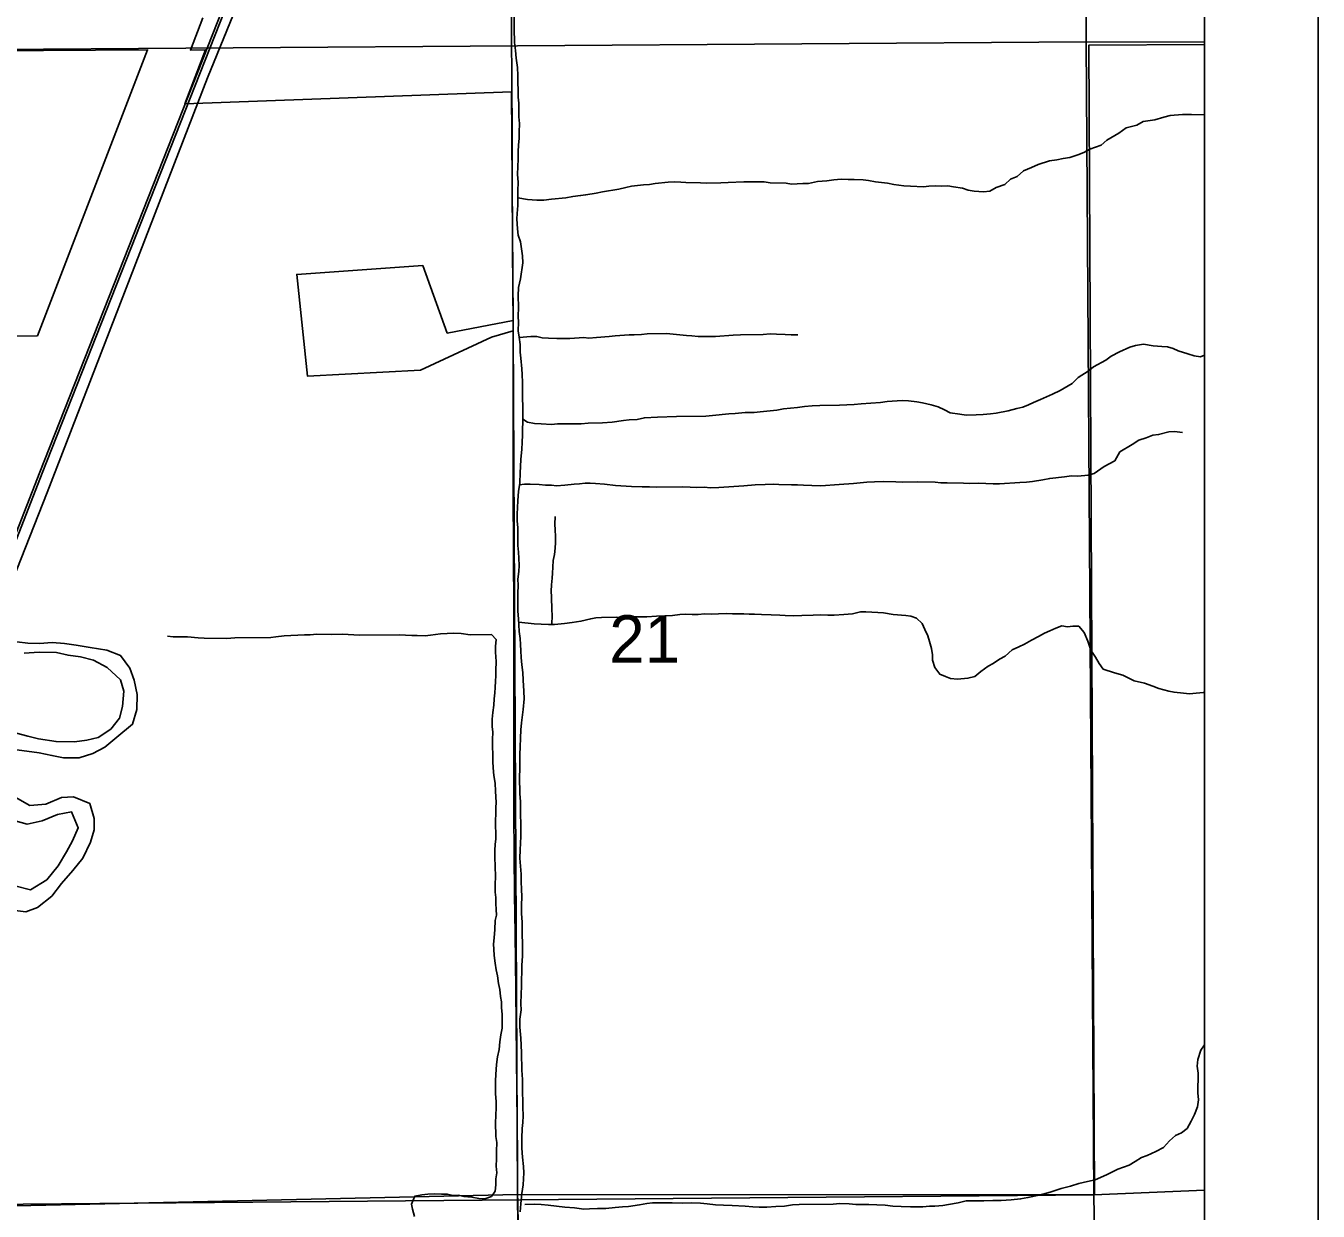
# Model space of a CAD drawing. Extents: x 0 to 34, y 0 to 22.
# Drawn here: x 7.864 to 9, y 17.862 to 18.904 of the extents above; entities that cross this region are included whole.
import ezdxf

# ---------------------------------------------------------------- set-up
doc = ezdxf.new("R2010")
doc.units = 0
for name, color, linetype in [('Default', 7, 'Continuous'), ('GM_X_County_Road', 7, 'Continuous'), ('GM_X_Minor_River', 7, 'Continuous'), ('GM_X_Rail_Line', 7, 'Continuous'), ('GM_X_Section', 7, 'Continuous'), ('GM_X_Section_Text', 7, 'Continuous'), ('GM_X_State_Route', 7, 'Continuous'), ('SH_Data', 7, 'Continuous')]:
    doc.layers.add(name, color=color, linetype=linetype)

msp = doc.modelspace()

# ---------------------------------------------------------------- linework, layer by layer
at = {"layer": 'Default'}
for points in [[(8.9, 18.8897), (8.9, 19.8895), (8.7909, 19.8887), (8.796, 18.8901)], [(8.9, 17.8804), (8.9, 18.8897), (8.796, 18.8901), (8.8027, 17.8763)], [(8.9, 16.8757), (8.9, 17.8804), (8.8027, 17.8763), (8.8106, 17.3801), (8.802, 16.8756)]]:
    msp.add_lwpolyline(points, close=True, dxfattribs=at)
for points in [[(7.7898, 17.3636), (8.3, 17.3879), (8.2997, 17.4193), (8.2996, 17.4628), (8.2992, 17.5498), (8.2973, 17.7551), (8.2966, 17.8142), (8.2964, 17.8483), (8.296, 17.8766), (8.2922, 18.636), (8.2732, 18.6304), (8.2109, 18.6013), (8.1114, 18.5961), (8.102, 18.6855), (8.2128, 18.6932), (8.2343, 18.6339), (8.2922, 18.6449), (8.2909, 18.8461), (8.0037, 18.8355), (8.0219, 18.883), (8.0085, 18.8827), (8.0194, 18.9112)], [(7.7881, 18.8817), (7.9709, 18.883), (7.874, 18.6316), (7.8353, 18.6309)]]:
    msp.add_lwpolyline(points, dxfattribs=at)
at = {"layer": 'GM_X_County_Road'}
msp.add_line((8.2924, 18.6354), (8.2924, 18.6444), dxfattribs=at)
for points in [[(8.2911, 18.8456), (8.2907, 18.906), (8.2905, 18.9401), (8.29, 19.0082), (8.2898, 19.0423), (8.2899, 19.0857), (8.2898, 19.1136), (8.2897, 19.1353), (8.29, 19.1539), (8.2902, 19.2096), (8.2895, 19.2654), (8.2896, 19.315), (8.2896, 19.3521), (8.2895, 19.3846)], [(8.2924, 18.6444), (8.2921, 18.6709), (8.2917, 18.7116), (8.2915, 18.7678), (8.2913, 18.8178), (8.2911, 18.8456)], [(8.2962, 17.8761), (8.2961, 17.91), (8.2952, 17.997), (8.2946, 18.0561), (8.294, 18.1059), (8.2936, 18.1401), (8.293, 18.2116), (8.2929, 18.2613), (8.2928, 18.3048), (8.2928, 18.3888), (8.2924, 18.4945), (8.2922, 18.5411), (8.2924, 18.5876), (8.2923, 18.6061), (8.2924, 18.6354)], [(8.3002, 17.3874), (8.2999, 17.4187), (8.2998, 17.4622), (8.2994, 17.5493), (8.2975, 17.7545), (8.2968, 17.8136), (8.2966, 17.8478), (8.2963, 17.8707), (8.2962, 17.8761)]]:
    msp.add_lwpolyline(points, dxfattribs=at)
at = {"layer": 'GM_X_Minor_River'}
for points in [[(8.2929, 18.9356), (8.2933, 18.9014), (8.2935, 18.8893), (8.2943, 18.8824), (8.2948, 18.8756), (8.296, 18.8673), (8.2965, 18.8604), (8.2967, 18.8414), (8.2972, 18.8361), (8.2974, 18.824), (8.2978, 18.8183), (8.2975, 18.8107), (8.2976, 18.805), (8.2969, 18.7993), (8.2966, 18.7932), (8.2967, 18.7867), (8.2964, 18.7803), (8.2961, 18.7734), (8.2966, 18.7666), (8.2963, 18.759), (8.2965, 18.7461), (8.2958, 18.7392), (8.2955, 18.7343), (8.296, 18.7256), (8.2968, 18.7199), (8.2988, 18.7142), (8.2996, 18.7081), (8.3005, 18.7017), (8.3009, 18.6956), (8.2988, 18.6815), (8.297, 18.6739), (8.2967, 18.6667), (8.2969, 18.6568), (8.2966, 18.6485), (8.297, 18.6435), (8.2968, 18.6359), (8.2976, 18.6302), (8.2984, 18.6238), (8.2985, 18.617), (8.299, 18.612), (8.2998, 18.6025), (8.3003, 18.5976)], [(8.2964, 18.7529), (8.3048, 18.7515), (8.3131, 18.7509), (8.3192, 18.7509), (8.3261, 18.7518), (8.3386, 18.7527), (8.3447, 18.7539), (8.3515, 18.7548), (8.3561, 18.7556), (8.3652, 18.7569), (8.3709, 18.7581), (8.3853, 18.7606), (8.3913, 18.7618), (8.3963, 18.763), (8.4069, 18.7643), (8.4122, 18.7647), (8.4172, 18.7655), (8.4286, 18.7665), (8.4339, 18.7669), (8.4396, 18.7666), (8.4442, 18.7663), (8.4571, 18.7661), (8.4624, 18.7658), (8.475, 18.7659), (8.4814, 18.7664), (8.4951, 18.767), (8.5004, 18.767), (8.513, 18.7668), (8.5183, 18.7661), (8.5324, 18.7656), (8.537, 18.7649), (8.5469, 18.7654), (8.5518, 18.7654), (8.5598, 18.7671), (8.5681, 18.7679), (8.5742, 18.7688), (8.5807, 18.7692), (8.5867, 18.7689), (8.5921, 18.769), (8.6001, 18.7687), (8.6046, 18.768), (8.6107, 18.767), (8.6214, 18.7656), (8.6271, 18.7645), (8.6359, 18.7635), (8.6416, 18.7632), (8.653, 18.7626), (8.6576, 18.763), (8.6633, 18.7635), (8.669, 18.7632), (8.6743, 18.7633), (8.6793, 18.7626), (8.6873, 18.7612), (8.6922, 18.7597), (8.6976, 18.7586), (8.7059, 18.758), (8.7113, 18.7588), (8.7169, 18.7619), (8.7245, 18.7647), (8.7294, 18.7693), (8.7354, 18.7717), (8.7411, 18.7767), (8.7479, 18.7794), (8.7539, 18.7822), (8.7638, 18.7853), (8.7702, 18.7862), (8.7759, 18.7874), (8.7816, 18.7882), (8.7888, 18.7906), (8.7941, 18.7926), (8.7994, 18.7957), (8.8092, 18.7992), (8.8141, 18.8035), (8.8247, 18.8097), (8.8311, 18.8144), (8.8406, 18.8168), (8.8462, 18.8199), (8.8565, 18.8215), (8.8644, 18.8239), (8.8698, 18.8251), (8.8808, 18.826), (8.8888, 18.8261), (8.8998, 18.8259), (8.9, 18.8259)], [(8.2976, 18.63), (8.3079, 18.6308), (8.3132, 18.6308), (8.3178, 18.6298), (8.3235, 18.6295), (8.3307, 18.6292), (8.3421, 18.6293), (8.3543, 18.6299), (8.3588, 18.6295), (8.3657, 18.63), (8.3767, 18.6309), (8.382, 18.6314), (8.3942, 18.6323), (8.3987, 18.6323), (8.4052, 18.6328), (8.4101, 18.6333), (8.4272, 18.6335), (8.4448, 18.6318), (8.4493, 18.6315), (8.455, 18.6308), (8.4703, 18.631), (8.4858, 18.632), (8.4923, 18.6325), (8.5121, 18.6327), (8.5181, 18.6332), (8.5239, 18.6329), (8.5315, 18.6326), (8.5368, 18.6323), (8.5425, 18.6324)], [(8.3008, 18.5581), (8.305, 18.5555), (8.3111, 18.5545), (8.3168, 18.5542), (8.326, 18.5535), (8.3313, 18.554), (8.3522, 18.5542), (8.3583, 18.5547), (8.3708, 18.5549), (8.3792, 18.5557), (8.3894, 18.557), (8.3944, 18.5575), (8.4012, 18.5579), (8.4077, 18.5595), (8.4191, 18.5601), (8.4358, 18.5607), (8.4617, 18.561), (8.4674, 18.5615), (8.4818, 18.5628), (8.4875, 18.5633), (8.4962, 18.5641), (8.5042, 18.5642), (8.5095, 18.5647), (8.524, 18.566), (8.53, 18.5672), (8.5422, 18.5685), (8.5483, 18.5694), (8.5551, 18.5699), (8.5619, 18.5703), (8.5791, 18.5706), (8.592, 18.5711), (8.5981, 18.5716), (8.6068, 18.5724), (8.6152, 18.5729), (8.6212, 18.5738), (8.6342, 18.5747), (8.6399, 18.5744), (8.6471, 18.5734), (8.6521, 18.5727), (8.6597, 18.5709), (8.6658, 18.569), (8.6715, 18.5665), (8.6765, 18.5639), (8.6849, 18.5625), (8.6906, 18.5618), (8.6994, 18.5619), (8.7054, 18.5624), (8.7119, 18.5628), (8.7168, 18.5636), (8.7275, 18.5657), (8.735, 18.5677), (8.7403, 18.5689), (8.7453, 18.5709), (8.7498, 18.5728), (8.7559, 18.5756), (8.7664, 18.5803), (8.7732, 18.5834), (8.7838, 18.5896), (8.7891, 18.595), (8.7977, 18.6004), (8.8026, 18.6043), (8.8132, 18.6101), (8.8181, 18.6136), (8.8253, 18.6175), (8.8344, 18.6214), (8.8393, 18.623), (8.8465, 18.6242), (8.8549, 18.6228), (8.8625, 18.6222), (8.8675, 18.6219), (8.8724, 18.6204), (8.877, 18.6182), (8.8854, 18.6156), (8.8911, 18.6138), (8.8965, 18.6131), (8.9, 18.6146)], [(8.3003, 18.5976), (8.3004, 18.5904), (8.3008, 18.5555), (8.3005, 18.5494), (8.3006, 18.5441), (8.3003, 18.538), (8.3, 18.5315), (8.299, 18.5231), (8.2987, 18.5163), (8.2984, 18.5114), (8.2981, 18.5019), (8.2971, 18.4946), (8.2964, 18.4866), (8.2961, 18.4802), (8.2958, 18.4749), (8.2959, 18.4688), (8.2963, 18.4627), (8.2965, 18.4471), (8.297, 18.4414), (8.2974, 18.4361), (8.2975, 18.4297), (8.2972, 18.4244), (8.2965, 18.4175), (8.2966, 18.4122), (8.2963, 18.405), (8.2964, 18.397), (8.2965, 18.3894), (8.297, 18.3826), (8.2974, 18.3773), (8.2975, 18.3716), (8.2984, 18.3655), (8.2988, 18.3602), (8.2989, 18.3545), (8.2993, 18.3488), (8.2998, 18.3423), (8.3007, 18.3355), (8.3011, 18.3287), (8.3016, 18.3192), (8.3021, 18.3124), (8.3011, 18.3029), (8.2997, 18.2911), (8.299, 18.285), (8.2987, 18.2778), (8.2985, 18.2702), (8.2982, 18.2633), (8.2983, 18.2508), (8.298, 18.2436), (8.2982, 18.2291), (8.2987, 18.2219), (8.2991, 18.1912), (8.2985, 18.1797), (8.2982, 18.1721), (8.2987, 18.1653), (8.2992, 18.1581), (8.2992, 18.1509), (8.2997, 18.1456), (8.2998, 18.1376), (8.2995, 18.1315), (8.2996, 18.1235), (8.3001, 18.116), (8.3005, 18.0863), (8.2998, 18.078), (8.2999, 18.0726), (8.2996, 18.065), (8.2997, 18.0593), (8.2994, 18.0529), (8.2991, 18.0441), (8.2992, 18.0388), (8.2981, 18.0308), (8.2982, 18.0236), (8.2991, 18.0141), (8.2992, 18.0077), (8.2997, 18.0012), (8.2999, 17.9857), (8.3004, 17.9777), (8.3004, 17.9716), (8.3007, 17.9534), (8.3012, 17.9458), (8.3009, 17.9397), (8.3002, 17.9344), (8.2999, 17.926), (8.3, 17.9173), (8.3005, 17.9093), (8.3014, 17.901), (8.3018, 17.8957), (8.3012, 17.885), (8.2998, 17.8774), (8.2991, 17.8683), (8.2984, 17.8614)], [(8.2979, 18.5004), (8.3023, 18.5012), (8.3073, 18.5012), (8.3152, 18.5009), (8.3206, 18.5003), (8.3259, 18.5003), (8.3305, 18.4996), (8.3377, 18.5001), (8.346, 18.501), (8.3506, 18.5014), (8.3555, 18.5019), (8.3601, 18.5019), (8.3647, 18.5016), (8.3727, 18.501), (8.3822, 18.4999), (8.3963, 18.499), (8.4058, 18.4987), (8.4123, 18.4988), (8.418, 18.4985), (8.4412, 18.4988), (8.448, 18.4985), (8.4537, 18.4982), (8.4602, 18.4983), (8.4659, 18.498), (8.4731, 18.4981), (8.4819, 18.4986), (8.4952, 18.4995), (8.505, 18.5004), (8.5138, 18.5009), (8.521, 18.501), (8.526, 18.5007), (8.537, 18.5005), (8.5423, 18.5006), (8.5476, 18.5002), (8.5549, 18.5), (8.5629, 18.4997), (8.5788, 18.5007), (8.5914, 18.5016), (8.6031, 18.5029), (8.61, 18.503), (8.6176, 18.5034), (8.6286, 18.5032), (8.6347, 18.5029), (8.648, 18.5031), (8.6632, 18.5029), (8.6682, 18.5022), (8.6739, 18.5023), (8.6883, 18.5021), (8.6937, 18.5018), (8.7013, 18.5019), (8.7142, 18.5013), (8.7199, 18.5014), (8.7378, 18.5024), (8.7435, 18.5028), (8.7488, 18.5033), (8.7579, 18.5049), (8.764, 18.5062), (8.7769, 18.5075), (8.7833, 18.5083), (8.7887, 18.508), (8.7978, 18.5089), (8.8031, 18.5105), (8.8118, 18.5167), (8.8212, 18.5217), (8.8257, 18.5294), (8.8366, 18.536), (8.8423, 18.5399), (8.8487, 18.5418), (8.8548, 18.5442), (8.8597, 18.5447), (8.8688, 18.5471), (8.8737, 18.5475), (8.8806, 18.5465)], [(8.3264, 18.3776), (8.3266, 18.386), (8.3262, 18.3906), (8.326, 18.4019), (8.3256, 18.4069), (8.3259, 18.4126), (8.3266, 18.4183), (8.3269, 18.4229), (8.3272, 18.4282), (8.3275, 18.4339), (8.3286, 18.4392), (8.3293, 18.4449), (8.3296, 18.4499), (8.3295, 18.4552), (8.3291, 18.4609), (8.329, 18.4658), (8.3293, 18.4726)], [(8.2972, 18.3798), (8.3107, 18.3782), (8.3168, 18.3779), (8.3233, 18.3776), (8.3286, 18.3777), (8.3374, 18.3785), (8.3442, 18.3794), (8.3518, 18.3806), (8.3605, 18.3827), (8.3651, 18.3835), (8.37, 18.3839), (8.3833, 18.3841), (8.3913, 18.3838), (8.3989, 18.3843), (8.4099, 18.3845), (8.4183, 18.3849), (8.4255, 18.3854), (8.4324, 18.3855), (8.4388, 18.3864), (8.4441, 18.3868), (8.4498, 18.3865), (8.4548, 18.3866), (8.4605, 18.387), (8.4666, 18.3867), (8.4727, 18.3872), (8.4795, 18.3873), (8.4852, 18.387), (8.4902, 18.387), (8.4951, 18.3871), (8.4997, 18.3868), (8.5046, 18.3869), (8.5107, 18.3866), (8.5191, 18.3863), (8.5267, 18.386), (8.5313, 18.3857), (8.5389, 18.3854), (8.5461, 18.3855), (8.556, 18.386), (8.5621, 18.3861), (8.5689, 18.3858), (8.5746, 18.3859), (8.583, 18.3864), (8.5906, 18.3872), (8.5978, 18.3888), (8.6023, 18.3889), (8.613, 18.3883), (8.6179, 18.388), (8.6263, 18.3866), (8.6374, 18.3856), (8.6419, 18.3849), (8.6469, 18.3834), (8.6519, 18.3786), (8.6543, 18.3733), (8.657, 18.3676), (8.6582, 18.3627), (8.6602, 18.3566), (8.661, 18.3509), (8.6611, 18.3464), (8.6631, 18.34), (8.6673, 18.3339), (8.6723, 18.3321), (8.6769, 18.3303), (8.683, 18.3296), (8.6921, 18.3305), (8.6982, 18.3321), (8.7034, 18.3363), (8.7098, 18.341), (8.7144, 18.3433), (8.72, 18.3472), (8.7249, 18.3499), (8.7309, 18.3553), (8.737, 18.358), (8.7419, 18.3604), (8.7479, 18.3639), (8.754, 18.367), (8.7593, 18.3701), (8.7642, 18.3721), (8.7695, 18.3744), (8.7748, 18.3764), (8.7797, 18.3757), (8.7843, 18.3761), (8.7896, 18.3762), (8.7943, 18.3706), (8.7974, 18.363), (8.8002, 18.3551), (8.8044, 18.3491), (8.8075, 18.3434), (8.811, 18.3385), (8.821, 18.3352), (8.8282, 18.333), (8.8382, 18.3282), (8.8473, 18.3261), (8.8546, 18.3235), (8.8599, 18.3213), (8.8687, 18.3191), (8.8733, 18.3181), (8.8817, 18.3174), (8.887, 18.3167), (8.8927, 18.3172), (8.8992, 18.318), (8.9, 18.3181)], [(7.8561, 18.2676), (7.8755, 18.2648), (7.8868, 18.2626), (7.8971, 18.2604), (7.9107, 18.2605), (7.9228, 18.2644), (7.9334, 18.2697), (7.9439, 18.2785), (7.9575, 18.29), (7.9616, 18.303), (7.9618, 18.3162), (7.9591, 18.3287), (7.9552, 18.3393), (7.9472, 18.3503), (7.9351, 18.3551), (7.9203, 18.3576), (7.9081, 18.3594), (7.8979, 18.3609), (7.8869, 18.3619), (7.8759, 18.3611), (7.8657, 18.3614), (7.8559, 18.3625)], [(7.9884, 18.3674), (7.9933, 18.3668), (8.0059, 18.3669), (8.0154, 18.3659), (8.0207, 18.3656), (8.0405, 18.3655), (8.0477, 18.366), (8.0793, 18.3664), (8.0838, 18.3668), (8.0911, 18.3677), (8.1089, 18.3687), (8.1139, 18.3687), (8.1196, 18.3692), (8.1325, 18.369), (8.1424, 18.3691), (8.1572, 18.3682), (8.1922, 18.3686), (8.2032, 18.368), (8.2078, 18.3681), (8.215, 18.3678), (8.2196, 18.3682), (8.2283, 18.3695), (8.2401, 18.37), (8.2466, 18.3697), (8.2546, 18.3687), (8.2732, 18.369), (8.2775, 18.3645), (8.2768, 18.3584), (8.2768, 18.3534), (8.2773, 18.3451), (8.2771, 18.3371), (8.2771, 18.3325), (8.2768, 18.328), (8.2765, 18.3223), (8.2762, 18.3177), (8.2755, 18.3124), (8.2752, 18.3067), (8.2745, 18.3002), (8.2738, 18.2945), (8.2739, 18.2881), (8.2743, 18.2831), (8.274, 18.2767), (8.2743, 18.2573), (8.2747, 18.2516), (8.2752, 18.2448), (8.2764, 18.2383), (8.2769, 18.2311), (8.277, 18.2262), (8.2774, 18.2212), (8.2771, 18.2167), (8.2772, 18.211), (8.2769, 18.2057), (8.2771, 18.1893), (8.2764, 18.1844), (8.2761, 18.1794), (8.2761, 18.1741), (8.2766, 18.1639), (8.2767, 18.157), (8.2765, 18.1483), (8.2765, 18.1422), (8.277, 18.1377), (8.277, 18.1324), (8.2775, 18.127), (8.2776, 18.1221), (8.2765, 18.1175), (8.2762, 18.1096), (8.2755, 18.1023), (8.2749, 18.0966), (8.2753, 18.0921), (8.2757, 18.0868), (8.2766, 18.0799), (8.2774, 18.0742), (8.2786, 18.0689), (8.2795, 18.0621), (8.2807, 18.0568), (8.2812, 18.0507), (8.282, 18.0458), (8.282, 18.0409), (8.2825, 18.0348), (8.2827, 18.0227), (8.2816, 18.0169), (8.2805, 18.0108), (8.2799, 18.004), (8.2784, 17.9975), (8.2777, 17.9907), (8.2771, 17.9819), (8.2768, 17.9766), (8.2769, 17.9652), (8.2774, 17.958), (8.2775, 17.9535), (8.2772, 17.9455), (8.2769, 17.9401), (8.277, 17.9276), (8.2779, 17.9223), (8.2776, 17.9147), (8.2777, 17.9079), (8.2774, 17.9014), (8.2778, 17.8957), (8.2772, 17.8904), (8.2772, 17.8851), (8.2765, 17.8794)], [(7.8624, 18.3526), (7.8756, 18.3535), (7.8908, 18.3532), (7.901, 18.3507), (7.912, 18.3492), (7.9234, 18.3463), (7.9355, 18.3399), (7.947, 18.329), (7.9501, 18.3192), (7.949, 18.3055), (7.9461, 18.2953), (7.9386, 18.2857), (7.9276, 18.2784), (7.9174, 18.2761), (7.9068, 18.2745), (7.8905, 18.2747), (7.875, 18.2773), (7.8655, 18.2795), (7.8557, 18.2821)], [(7.8545, 18.1262), (7.8639, 18.1251), (7.8741, 18.129), (7.8866, 18.1389), (7.8952, 18.15), (7.9053, 18.1615), (7.914, 18.1721), (7.9207, 18.1862), (7.924, 18.1972), (7.924, 18.2071), (7.9201, 18.2203), (7.9057, 18.2263), (7.8951, 18.2255), (7.8815, 18.2197), (7.8675, 18.2184), (7.8545, 18.2259)], [(7.8513, 18.2058), (7.8649, 18.2021), (7.8782, 18.2052), (7.8917, 18.2107), (7.9039, 18.213), (7.91, 18.199), (7.9048, 18.1876), (7.8995, 18.1777), (7.8924, 18.1655), (7.8823, 18.1533), (7.868, 18.1445), (7.8543, 18.1478)], [(8.3025, 17.8676), (8.3109, 17.868), (8.317, 17.8677), (8.3231, 17.8671), (8.3376, 17.8654), (8.3463, 17.8647), (8.3543, 17.8637), (8.3593, 17.8638), (8.3665, 17.8642), (8.3737, 17.8643), (8.3821, 17.8652), (8.3885, 17.8657), (8.3938, 17.8661), (8.4033, 17.8674), (8.4098, 17.8686), (8.4147, 17.8691), (8.4322, 17.8693), (8.441, 17.869), (8.4493, 17.8691), (8.4569, 17.8688), (8.463, 17.8682), (8.4703, 17.8675), (8.4771, 17.8672), (8.4847, 17.8669), (8.4962, 17.8663), (8.503, 17.8657), (8.5087, 17.8654), (8.5152, 17.8654), (8.5232, 17.8659), (8.5308, 17.8664), (8.538, 17.8673), (8.5437, 17.8677), (8.5737, 17.8681), (8.5794, 17.8686), (8.5878, 17.8683), (8.5935, 17.8676), (8.6049, 17.8678), (8.6121, 17.8675), (8.6194, 17.8672), (8.6262, 17.8662), (8.6335, 17.8659), (8.6415, 17.8656), (8.6525, 17.8658), (8.6582, 17.8662), (8.6631, 17.8663), (8.67, 17.8667), (8.6749, 17.8676), (8.6836, 17.8692), (8.6905, 17.8708), (8.706, 17.871), (8.714, 17.8711), (8.7213, 17.8712), (8.73, 17.8717), (8.7384, 17.8726), (8.7448, 17.8738), (8.7547, 17.8758), (8.7645, 17.8786), (8.774, 17.8818), (8.7823, 17.8838), (8.7895, 17.8862), (8.7971, 17.8878), (8.8039, 17.8894), (8.8138, 17.8937), (8.824, 17.8988), (8.8338, 17.9023), (8.8391, 17.9055), (8.8448, 17.909), (8.8497, 17.9109), (8.8572, 17.9144), (8.864, 17.9179), (8.8693, 17.9237), (8.8746, 17.9283), (8.8799, 17.9307), (8.8847, 17.9346), (8.8885, 17.9411), (8.8914, 17.9468), (8.894, 17.9537), (8.8947, 17.9598), (8.8942, 17.9658), (8.8942, 17.9715), (8.8945, 17.9776), (8.8944, 17.9833), (8.8935, 17.9894), (8.8942, 17.9951), (8.8968, 18.0035), (8.9, 18.0081)], [(8.2765, 17.8794), (8.2732, 17.8748), (8.2675, 17.8728), (8.2622, 17.8731), (8.2561, 17.8742), (8.2488, 17.8748), (8.2442, 17.8759), (8.2397, 17.8755), (8.2343, 17.8769), (8.2294, 17.8768), (8.2229, 17.8771), (8.2172, 17.8767), (8.2119, 17.8762), (8.2058, 17.875), (8.2029, 17.8681), (8.2037, 17.8636), (8.2057, 17.8572)]]:
    msp.add_lwpolyline(points, dxfattribs=at)
at = {"layer": 'GM_X_Rail_Line'}
for points in [[(7.4155, 16.9797), (7.4558, 17.1778), (7.5178, 17.4999), (7.5426, 17.6225), (7.5717, 17.7043), (7.6321, 17.8584), (7.8825, 18.4937), (8.0236, 18.8584), (8.1515, 19.1722), (8.1675, 19.2314), (8.3282, 19.8945)], [(7.1956, 16.9797), (7.2748, 17.1151), (7.3911, 17.3137), (7.4282, 17.3794), (7.4457, 17.4145), (7.4643, 17.4578), (7.6315, 17.8854), (7.7259, 18.128), (7.7853, 18.2725), (7.8783, 18.5108), (8.1687, 19.2471)], [(7.7606, 18.2123), (7.7831, 18.2734), (7.8762, 18.5116), (8.1665, 19.2479)]]:
    msp.add_lwpolyline(points, dxfattribs=at)
at = {"layer": 'GM_X_Section'}
for points in [[(7.782, 19.8851), (8.7909, 19.8887), (8.796, 18.8901), (7.7959, 18.8831)], [(8.796, 18.8901), (8.8027, 17.8763), (7.7942, 17.8673), (7.7959, 18.8831)], [(7.9972, 16.8792), (8.802, 16.8756), (8.8106, 17.3801), (8.8027, 17.8763), (7.7942, 17.8673), (7.7942, 17.5709), (7.8062, 16.9797), (7.9972, 16.9797)]]:
    msp.add_lwpolyline(points, close=True, dxfattribs=at)
at = {"layer": 'GM_X_State_Route'}
msp.add_lwpolyline([(5.7774, 16.9797), (7.8038, 16.9797), (7.7904, 17.865), (8.296, 17.8766), (8.8033, 17.8763), (8.7984, 18.8872), (8.9, 18.8876), (8.9, 20.9), (5.6507, 20.9)], dxfattribs=at)
msp.add_lwpolyline([(7.8042, 16.2626), (7.8024, 15.8725), (6.7968, 15.8774), (5.6416, 15.8841), (5.6436, 15.468), (5.6455, 14.1), (8.9, 14.1), (8.9, 18.8876), (8.7984, 18.8872), (8.8033, 17.8763), (8.296, 17.8766), (7.7904, 17.865), (7.8038, 16.9797), (7.9972, 16.9797), (7.9972, 16.2626)], close=True, dxfattribs=at)
at = {"layer": 'SH_Data'}
for p, q in [((9, 21), (9, 14)), ((8.9, 20.9), (8.9, 14.1))]:
    msp.add_line(p, q, dxfattribs=at)

# ---------------------------------------------------------------- texts
at = {"layer": 'GM_X_Section_Text'}
msp.add_text('21', height=0.04186, rotation=0, dxfattribs=at).set_placement((8.3768, 18.344))

doc.saveas('drawing.dxf')
